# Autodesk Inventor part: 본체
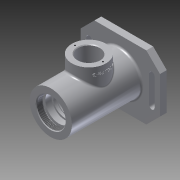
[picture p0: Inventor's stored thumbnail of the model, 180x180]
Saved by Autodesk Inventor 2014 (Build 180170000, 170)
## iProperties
Created: 2017-10
Part Number: 본체
Material: 알루미늄 6061
Document SubType Name: Modeling
Designer: net
Mass: 738.275 g
Surface Area: 652.722 cm^2
Volume: 272.426 cm^3
Density: 2.71 g/cm^3
Appearance: 알루미늄 - 평지
Author: net
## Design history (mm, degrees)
sketch "스케치1"
  geometry: L1 (0, 0)-(-115, 0); L2 (-115, 0)-(-115, 31); L3 (-115, 31)-(-13, 31); L4 (-13, 31)-(-13, 31); L5 (-13, 31)-(-3, 31); L6 (-3, 31)-(-3, 35); L7 (-3, 35)-(0, 35); L8 (0, 35)-(0, 0); L9 (-115, 21)-(-106, 21); L10 (-106, 21)-(-106, 24); L11 (-106, 24)-(-103, 24); L12 (-103, 24)-(-103, 20); L13 (-103, 20)-(-94, 20); L14 (-94, 20)-(-94, 17.5); L15 (-94, 17.5)-(-90.75, 17.5); L16 (-90.75, 17.5)-(-90.75, 18.5); L17 (-90.75, 18.5)-(-89, 18.5); L18 (-89, 18.5)-(-89, 17.5); L19 (-89, 17.5)-(-78, 17.5); L20 (-78, 17.5)-(-78, 26); L21 (-78, 26)-(-40, 26); L22 (-40, 26)-(-40, 17.5); L23 (-40, 17.5)-(-29, 17.5); L24 (0, 22)-(-14, 16); L25 (-29, 17.5)-(-29, 16.5); L26 (-29, 16.5)-(-24, 16.5); L27 (-24, 16.5)-(-24, 10); L28 (-24, 10)-(-21.3, 10); L29 (-21.3, 10)-(-21.3, 12.5); L30 (-21.3, 12.5)-(-14.7, 12.5); L31 (-14.7, 12.5)-(-14, 12.904); L32 (-14, 12.904)-(-14, 16); 1 further point
  constraints: 64 end point, 16 perpendicular, 10 parallel, 3 horizontal, 2 point on line, 1 coincident, 1 vertical
  dimensions: "d0" = 115 distance of L1.start L1.end; "d1" = 3 distance of L6.end L7.end; "d2" = 13 distance between parallel lines of L4 L8; "d3" = 70 diameter of L7 L1; "d4" = 62 diameter of L3 L1; "d5" = 62 diameter of L5 L1; "d6" = 42 diameter of L9 L1; "d7" = 48 diameter of L11 L1; "d8" = 40 diameter of L13 L1; "d9" = 35 diameter of L15 L1; "d10" = 3 distance of L10.end L11.end; "d11" = 12 distance between parallel lines of L2 L12; "d12" = 21 distance between parallel lines of L2 L14; "d14" = 1.75 distance of L16.end L17.end; "d15" = 37 diameter of L17 L1; "d16" = 26 distance between parallel lines of L2 L18; "d17" = 11 distance of L18.end L19.end; "d18" = 35 diameter of L19 L1; "d19" = 38 distance of L20.end L21.end; "d20" = 52 diameter of L21 L1; "d21" = 11 distance of L22.end L23.end; "d22" = 35 diameter of L23 L1; "d23" = 44 diameter of L24.start L1; "d24" = 32 diameter of L24.end L1; "d25" = 14 horizontal distance of L24.start L24.end; "d26" = 5 distance of L25.end L26.end; "d27" = 33 diameter of L26 L1; "d28" = 2.7 distance of L27.end L28.end; "d29" = 20 diameter of L28 L1; "d30" = 0.7 horizontal distance of L31.end L30.end; "d31" = 30 deg angle of L30 L31; "d32" = 25 diameter of L30 L1
revolve "회전1" sketch "스케치1" stored, may be unused: angle "d33" = 90 deg
fillet "모깎기1" dims "d34" = 0.3
fillet "모깎기2" dims "d35" = 0.3
fillet "모깎기3" dims "d36" = 3
fillet "모깎기4" dims "d37" = 3
feature "스레드1" dims "d38" = 10, "d39" = 0
node "작업 평면1"
sketch "스케치3"
  geometry: L1 (-115, -31)-(-115, 31) reference; C1 r 25 at (-59, 0); 1 further point
  constraints: 1 centre point, 1 horizontal alignment
  dimensions: "d41" = 50 diameter of C1; "d42" = 56 distance from line of C1.centre L1
extrude "돌출1" join sketch "스케치3" stored distance "d43" = 10; taper "d44" = 0 deg
sketch "스케치4"
  geometry: C1 r 25 at (0, 0) reference; C2 r 16 at (0, 0); 1 further point
  constraints: 1 centre point, 1 coincident
  dimensions: "d45" = 32 diameter of C2
extrude "돌출2" cut sketch "스케치4" stored distance "d46" = 10; taper "d47" = 0 deg
sketch "스케치5" dims "d48" = 41
  geometry: C1 r 25 at (0, 0) reference; 3 further points
  constraints: 2 vertical alignment, 1 coincident, 2 other
hole "구멍1" sketch "스케치5" at (0, 20.5) diameter "d49" = 2.459; stored, may be unused: countersink angle "d53" = 90 deg, drill point angle "d55" = 118 deg; dims "d50" = 6, "d51" = 4, "d52" = 2, "d54" = 8
node "작업 평면2"
sketch "스케치6"
  geometry: L1 (47, -58)-(-47, -58); L2 (-47, -58)-(-47, 58); L3 (-47, 58)-(47, 58); L4 (47, 58)-(47, -58); L5 (47, -58)-(-47, 58); L6 (-47, -58)-(47, 58); C1 r 31 at (0, 0) reference; C2 r 16.429 at (0, 0) reference; 1 further point
  constraints: 12 end point, 2 midpoint, 2 parallel, 1 horizontal, 1 perpendicular
  dimensions: "d60" = 94 distance of L2.end L3.end; "d61" = 116 distance of L1.end L2.end
extrude "돌출3" join sketch "스케치6" distance "d62" = 10; taper "d63" = 0 deg
sketch "스케치7"
  geometry: L1 (-47, -58)-(47, -58) reference; L2 (47, -58)-(47, 58) reference; L3 (-47, 58)-(-47, -58) reference; L4 (-20, 46)-(20, 46); L5 (-20, 42)-(20, 42); L6 (20, 50)-(-20, 50); L7 (-47, 0)-(47, 0); L8 (-20, -42)-(20, -42); L9 (20, -50)-(-20, -50); C1 r 35 at (0, 0) reference; A1 r 4 centre (-20, 46) between (-20, 50) and (-20, 42); A2 r 4 centre (20, 46) between (20, 42) and (20, 50); A3 r 4 centre (-20, -46) between (-20, -42) and (-20, -50); A4 r 4 centre (20, -46) between (20, -50) and (20, -42); 1 further point
  constraints: 14 end point, 8 point on circle, 6 symmetric about line, 4 centre point, 4 tangent, 3 midpoint, 2 parallel, 1 vertical alignment, 2 other
  dimensions: "d64" = 40 distance of L4.start L4.end; "d65" = 46 distance from line of C1.centre L4; "d66" = 4 radius of A1
extrude "돌출4" cut sketch "스케치7" stored distance "d67" = 10; taper "d68" = 0 deg
chamfer "모따기1" distance "d69" = 20; stored, may be unused: second distance "d70" = 2, angle "d71" = 45 deg
fillet "모깎기5" dims "d72" = 3
chamfer "모따기2" distance "d73" = 1; stored, may be unused: second distance "d74" = 2, angle "d75" = 45 deg
chamfer "모따기3" distance "d76" = 1; stored, may be unused: second distance "d77" = 2, angle "d78" = 45 deg
node "작업 평면3"
sketch "스케치9"
  geometry: L1 (-115, -31)-(-115, 31) reference; L2 (-84, 47)-(-34, 47) reference; 2 further points
  constraints: 1 other
  dimensions: "d80" = 56 distance from line of L1 point (-59, 37); "d81" = 10 distance from line of point (-59, 37) L2
feature "엠보싱1" sketch "스케치9" dims "d16" = 26, "d82" = 0.5, "d83" = 0
fillet "모깎기6" dims "d84" = 3
node "솔리드1"
pattern_circular "원형 패턴1" dims angle "d57" = 360 deg
node "절단 모서리 투영1"
other parameters: "d40" = 47, "d59" = -13, "d79" = -25
